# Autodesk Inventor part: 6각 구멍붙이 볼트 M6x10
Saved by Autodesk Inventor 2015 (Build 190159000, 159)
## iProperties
Created: 2026-05
Part Number: 6각 구멍붙이 볼트 M6x10
Material: 일반
Document SubType Name: Modeling
Designer: 104
Density: 1 g/cm^3
Appearance: 기본값
Author: 104
Author: jhkim
Description: 6각머리 태핑 나사
Creation Date: 2026-04-27
Sending System: Autodesk Inventor 2027
Preprocessor: ST-DEVELOPER v20.1
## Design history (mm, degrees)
node "6각 구멍붙이 볼트 M6x101"
body "Solid1"
node "기준1"
